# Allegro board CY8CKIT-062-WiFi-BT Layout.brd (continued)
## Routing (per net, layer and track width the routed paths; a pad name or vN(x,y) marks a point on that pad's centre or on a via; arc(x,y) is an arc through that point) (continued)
VDD_NS: length 21.2
  TOP w0.203: 81.74,45.44 81.74,44.48 U1.J1
  TOP w0.254: C24.1 82.26,45.97 81.74,45.44
  TOP w0.381: C18.1 C24.1
  L03_SIG w0.381: TP3.1 v1(69.95,53.97)
  L06_SIG w0.381: v1(69.95,53.97) 75.26,53.97 77.01,52.21 80.54,52.21 81.13,51.63 82.43,51.63 v1(82.5,51.56)
VDDA: length 35.5
  TOP w0.203: 89.61,37.46 89.38,37.46 88.98,37.06 87.21,37.06 U1.A12 ; U1.A13 87.12,36.68 88.98,36.68 89.5,36.15 89.61,36.15
  TOP w0.381: 89.61,36.15 C37.1 C38.1 ; C36.1 C35.1 89.61,37.46
  L06_SIG w0.381: TP26.1 117.78,35.48 111.23,35.48 108.97,37.73 v1(93.76,37.73)
VDDD: length 27.8
  TOP w0.203: 87.34,44.93 87.34,44.7 U1.A1 ; U1.L4 v2(80.25,42.15) ; U1.C4 v2(85.45,42.15) ; U1.K12 v2(80.9,36.95)
  TOP w0.254: C26.1 87.34,44.93
  TOP w0.381: C26.1 C20.1
  L05_MIX w0.381: 110.77,59.12 TP2.1 ; TP2.1 111.86,58.03 ; TP2.1 111.86,60.22 ; TP2.1 112.95,59.12
  BOTTOM w0.254: v2(85.45,42.15) 85.45,41.68 C100.1 ; v2(80.25,42.15) 80.58,42.15 81.25,41.49 C101.1 ; v2(80.9,36.95) 80.96,36.89 C114.1
  BOTTOM w0.381: v1(105.77,53.62) 104.37,53.62 SW7.1 ; v1(78.33,51.5) 78.71,51.88 R91.1 ; v1(82.25,39.09) v1(81.1,39.09) 81.25,39.24 C105.1 C101.1 ; R147.1 78.97,31.92 v1(78.97,32.58) ; v1(83.9,39.09) v1(85.17,39.09) 85.02,39.24 C104.1 C100.1 ; v1(80.65,32.94) 80.76,33.05 v1(80.76,34.01) 80.96,34.21 C117.1 C114.1
  vias: v1(86.84,51.66) v1(88.34,51.66)
VDDUSB: length 6
  TOP w0.203: U1.M1 79.45,44.82 79.45,45.06
  TOP w0.254: 79.45,46.96 79.45,45.06
  TOP w0.381: 79.45,46.96 C22.1 78.82,46.98 C21.1 ; 72.49,47.42 TP10.1 73.36,46.55
VIN: length 51.4
  TOP w0.381: v1(11.98,46.69) 11.8,46.87 R16.1
  L03_SIG w0.381: v1(13.79,10.77) 13.79,44.87 v1(11.98,46.69)
  L04_MIX w0.381: 4.74,2.36 J9.2 2.27,2.36 ; 45.16,15.65 J1.1 ; J1.1 45.16,17.83 ; J1.1 46.25,16.74
  BOTTOM w0.381: 45.16,15.65 J1.1 ; J1.1 44.07,16.74 ; J1.1 45.16,17.83 ; J1.1 46.25,16.74
  BOTTOM w0.635: 1.75,2.35 1.76,2.36 J9.2 5.05,2.36 5.05,2.35
  vias: v1(5.18,3.24) v1(7.34,1.85) v1(13.56,1.97) v1(17.5,2.23) v1(26.52,11.63) v1(29.57,11.63) v1(32.49,11.63) v1(45.57,18.86) v1(46.33,18.86) v1(47.6,14.93) v1(47.73,17.47)
VIN_MON: length 5.6
  TOP w0.254: U3.25 13.5,51.33 C15.1
  TOP w0.381: R16.2 12.84,49.31 R14.2 12.83,50.66 C15.1
ANT: length 3
  TOP w0.254: U6.41 122.22,57.9
  TOP w0.559: C4.2 122.22,58.96 L11.1 122.24,57.92 122.22,57.9
BT_DEV_WAKE_P4_0: length 61.2
  TOP w0.114: U1.L7 v2(80.25,40.2) ; U6.39 123.12,56.72 v1(122.78,56.38)
  L03_SIG w0.114: v1(122.78,56.38) 119.25,52.85 119.25,49.01 120.24,48.02 120.24,46.65 119.61,46.02 v1(119.61,45.03)
  L06_SIG w0.114: v2(80.25,40.2) 82.47,40.2 82.8,40.53 87.2,40.53 87.73,41.06 89.04,41.06 89.71,41.73 103.58,41.73 104.67,42.82 108.94,42.82 110.21,41.55 113.92,41.55 115.01,42.64 116.31,42.64 118.66,45 119.58,45 v1(119.61,45.03)
  BOTTOM w0.114: TP35.1 121.95,54.4 121.95,55.54 v1(122.78,56.38)
BT_GPIO_3: length 22.7
  TOP w0.114: TP22.1 123.42,37.15 v1(123.16,37.15) ; U6.6 121.41,54.3 121.11,54 120.51,54 118.24,51.73 118.24,48.56 v1(118.72,48.07)
  BOTTOM w0.114: v1(118.72,48.07) 118.72,47.55 120.14,46.13 120.31,46.13 120.6,45.83 120.6,43.65 122.91,41.34 122.91,37.41 v1(123.16,37.15)
BT_GPIO_4: length 25.8
  TOP w0.114: v1(123.16,36.26) 125.07,36.26 TP23.1 ; v1(119.23,46.3) 119.2,46.32 119.2,48.27 118.5,48.97 118.5,51.62 120.56,53.67 121.29,53.67 121.47,53.85 U6.7
  BOTTOM w0.114: v1(123.16,36.26) 122.66,36.77 122.66,41.22 119.1,44.77 119.1,46.17 v1(119.23,46.3)
BT_GPIO_5: length 14.4
  TOP w0.114: v1(122.4,48.05) 122.17,48.28 122.17,51.32 U6.13 ; TP17.1 125.7,41.47 v1(123.67,41.47)
  L03_SIG w0.114: v1(123.67,41.47) 124.11,41.91 124.11,45.83 122.4,47.54 v1(122.4,48.05)
BT_HOST_WAKE_P3_5: length 63.6
  TOP w0.114: U6.38 123.57,57.76 123.7,57.88 v1(123.7,57.88) ; v1(78.46,40.33) 79.23,41.1 U1.N6
  L03_SIG w0.114: v1(119.76,49.85) 120.57,50.67 120.57,53.38 123.39,56.2 123.39,57.58 v1(123.7,57.88)
  L06_SIG w0.114: v1(78.46,40.33) 78.79,40.66 78.79,43.74 80.77,45.71 87.15,45.71 87.7,45.16 91.4,45.16 92.96,46.73 94.52,46.73 95.07,46.17 110.18,46.17 111.25,47.24 113.65,47.24 116.51,50.11 119.51,50.11 v1(119.76,49.85)
  BOTTOM w0.114: v1(123.7,57.88) 123.2,57.38 122.94,57.38 TP31.1
BT_I2S_DO: length 16
  TOP w0.114: TP18.1 127.99,41.72 v1(127.99,42.87) ; v1(123.37,48.07) 122.85,48.59 122.85,49.54 123.57,50.26 U6.16
  L03_SIG w0.114: v1(127.99,42.87) 127.61,42.49 125.2,42.49 124.84,42.84 124.84,46.6 v1(123.37,48.07)
BT_PCM_CLK: length 18.8
  TOP w0.114: U6.11 120.75,52.05 120.37,51.66 120.37,51 121.21,50.16 121.21,47.44 123.72,44.92 130.23,44.92 131.8,43.35 TP15.1
BT_PCM_IN: length 16.4
  TOP w0.114: TP13.1 126.06,43.65 123.75,43.65 120.29,47.11 120.29,48 119.02,49.27 119.02,51.45 120.52,52.95 U6.9
BT_PCM_OUT: length 19
  TOP w0.114: U6.10 120.44,52.5 119.28,51.33 119.28,49.52 119.66,49.14 v1(120.07,49.14) ; TP14.1 v1(129.16,42.99)
  L06_SIG w0.114: v1(129.16,42.99) 129.18,42.99 129.18,44.21 128.12,45.28 122.66,45.28 121.06,46.88 121.06,48.15 v1(120.07,49.14)
BT_PCM_SYNC: length 24
  TOP w0.114: TP24.1 127.74,39.44 125.96,39.44 125.45,39.95 v1(123.42,39.95) ; v1(119.74,47.19) 119.74,48.08 119.43,48.38 119.43,48.39 118.75,49.07 118.75,51.52 120.62,53.4 U6.8
  BOTTOM w0.114: v1(123.42,39.95) 123.16,40.2 123.16,41.47 120.85,43.78 120.85,46.07 v1(119.74,47.19)
BT_REG_ON_P3_4: length 50.4
  TOP w0.114: U6.14 v1(122.67,50.72) ; U1.M6 v2(79.6,40.85)
  L03_SIG w0.114: v1(122.67,50.72) 121.23,49.28 121.23,46.78 v1(120.12,45.66)
  L06_SIG w0.114: v2(79.6,40.85) 79.92,40.53 82.39,40.53 82.63,40.76 85.47,40.76 85.89,41.18 87.53,41.18 87.64,41.29 88.63,41.29 89.45,42.11 103.42,42.11 104.51,43.2 108.94,43.2 109.5,42.64 114.27,42.64 114.72,43.1 116.05,43.1 118.62,45.66 v1(120.12,45.66)
BT_UART_CTS: length 6.6
  TOP w0.114: U6.4 121.25,55.2 121.01,54.96 118.32,54.96 R202.2 116.26,57.02 TP42.1
BT_UART_RTS: length 3.7
  TOP w0.114: U6.5 121.28,54.75 120.88,54.35 119.84,54.35 TP43.1 118.8,53.31 R203.2
BT_UART_RXD: length 5.3
  TOP w0.114: U6.2 120.94,56.1 R200.2 120.25,56.81 120.02,57.04 120.02,58.64 TP40.1
BT_UART_TXD: length 6.2
  TOP w0.114: U6.3 120.33,55.65 R201.2 120.25,56.02 120.09,56.18 118.64,56.18 118.47,56.35 118.47,57.29 TP41.1
CAP_BUT0_P8_1: length 20.9
  TOP w0.203: R61.1 v1(95.2,19.15)
  L06_SIG w0.203: v1(95.2,19.15) 96.11,18.24 96.11,13.91 99.54,10.48 v1(102.21,10.48) ; v1(102.84,7.69) v1(109.19,7.69)
CAP_BUT1_P8_2: length 42.7
  TOP w0.178: R60.1 v1(95.15,21.06)
  L06_SIG w0.203: v1(130.02,7.69) v1(124.56,7.69) ; v1(123.55,10.48) 120.12,13.91 97.89,13.91 96.75,15.05 96.75,20.39 96.08,21.06 v1(95.15,21.06)
CAP_PROX_P8_0: length 12.7
  TOP w0.203: J13.1 J13.2 R64.1 R63.1
CAP_SEG0_P8_3: length 10.2
  TOP w0.178: R53.1 95.17,26.77 v1(95.17,26.76)
  L06_SIG w0.203: v1(95.17,26.76) 102.31,26.76 v1(103.48,25.6)
CAP_SEG1_P8_4: length 18.9
  TOP w0.178: v1(95.17,28.64) 95.14,28.68 R52.1
  L06_SIG w0.203: v1(95.17,28.64) 96.29,28.64 97.84,30.19 97.84,32.02 98.15,32.33 107.54,32.33 108.18,31.69 v1(108.18,30.04)
CAP_SEG2_P8_5: length 24.5
  TOP w0.178: R47.1 v1(95.25,30.58)
  L06_SIG w0.203: v1(95.25,30.58) 95.39,30.73 96.8,30.73 97.13,31.06 97.13,32.58 97.51,32.96 113.13,32.96 114.15,31.95 v1(114.15,30.04)
CAP_SEG3_P8_6: length 36.2
  TOP w0.178: R58.1 v1(95.15,24.87)
  L06_SIG w0.203: v1(120.24,18.74) 120.24,17.47 118.34,15.56 98.78,15.56 98.09,16.25 98.09,22.85 96.08,24.87 v1(95.15,24.87)
CAP_SEG4_P8_7: length 42.7
  TOP w0.178: R59.1 95.17,22.96 v1(95.17,22.95)
  L06_SIG w0.203: v1(126.21,18.74) 126.21,15.56 125.45,14.8 98.4,14.8 97.51,15.69 97.51,21.53 96.09,22.95 v1(95.17,22.95)
CAP_TX_P1_0: length 59.9
  TOP w0.203: R62.2 v1(93.81,15.82)
  L03_SIG w0.203: v1(105.89,6.55) v1(105.89,8.96) ; v1(93.81,15.82) 94.51,15.12 94.51,13.12 96.66,10.98 96.66,6.48 99.47,3.68 v1(104.24,3.68) 124.23,3.68 v1(127.23,6.67) v1(127.23,8.83) 127.23,14.7 v1(124,17.92)
CC1: length 31.3
  TOP w0.114: U3.5 22.36,50.83 v1(22.43,50.9) ; J10.A5 8.04,52.97 8.61,53.54 8.61,55.57 v1(8.1,56.08)
  BOTTOM w0.114: v1(22.43,50.9) 21.89,51.44 21.89,57.53 20.65,58.78 14.39,58.78 12.7,60.47 10.46,60.47 8.57,58.58 C60.1 8.84,57.29 TVS2.1 8.11,56.06 v1(8.1,56.08)
CC2: length 38.1
  TOP w0.114: U3.3 22.37,49.83 v1(22.43,49.89)
  L06_SIG w0.114: J10.B5 3.32,52.79 3.32,57.16 5.18,59.02 v1(10.62,59.02)
  BOTTOM w0.114: TVS2.2 9.49,57.3 C59.1 9.75,58.15 v1(10.62,59.02) 12.4,59.02 13.03,58.39 20.38,58.39 21.59,57.18 21.59,50.72 v1(22.43,49.89)
CCG_12V_EN: length 55.1
  TOP w0.114: v1(18.03,45.56) 18.24,45.77 U3.35
  L03_SIG w0.114: v1(6.96,47.19) 6.96,44.42 7.98,43.4 7.98,11.38 v1(8.84,10.52)
  L06_SIG w0.114: v1(6.96,47.19) 10.08,47.19 12.93,44.34 17.48,44.34 18.03,44.9 v1(18.03,45.56)
  BOTTOM w0.114: U31.4 9,10.68 v1(8.84,10.52) R184.2
CCG_LED: length 30.7
  TOP w0.114: v1(10.21,43.63) 11.35,42.49 15.98,42.49 17.15,43.66 17.15,44.99 17.27,45.11 17.27,46.35 17.74,46.82 U3.34 ; LED7.K v1(11.71,59.92)
  L03_SIG w0.114: v1(11.71,59.92) 11.71,58.92 10.02,57.23 10.02,49.38 10.32,49.09 10.32,43.74 v1(10.21,43.63)
CCG_O_EN: length 26.4
  TOP w0.114: U3.38 19.74,46.25 v1(19.76,46.23)
  L03_SIG w0.114: v1(20.02,56.06) 19.76,55.8 v1(19.76,46.23)
  L06_SIG w0.114: v1(20.02,56.06) 21.67,54.4 28.92,54.4 v1(30.18,55.65)
  BOTTOM w0.114: v1(30.18,55.65) U13.2 26.93,55.65 R84.2
CCG_SWDCLK: length 14.1
  TOP w0.114: U3.16 18.24,54.76 18.36,54.88 18.36,56.36 19.12,57.12 24.47,57.12 25.63,55.96 25.63,53.92 TP36.1
CCG_SWDIO: length 16
  TOP w0.114: TP38.1 24.41,51.33 23.83,51.92 23.83,52.95 25.35,54.48 25.35,55.8 24.28,56.87 19.28,56.87 18.74,56.33 U3.15
CCG_VBUS_OUT: length 38.5
  TOP w0.203: v1(21.03,45.44) 20.67,45.8 20.67,47.27 20.74,47.34 U3.40
  L03_SIG w0.203: v1(10.19,41.65) 10.55,42.01 11.59,42.01 12.37,41.23 12.37,31.26 10.11,29 10.11,27.08 10.57,26.62 11.02,26.62 v1(11.25,26.39)
  L06_SIG w0.203: v1(21.03,45.44) 20.62,45.03 20.62,44.35 19.28,43 15.28,43 14.27,41.99 10.52,41.99 v1(10.19,41.65)
  BOTTOM w0.203: R154.1 13.14,25.95 12.7,26.39 v1(11.25,26.39)
CCG_VCCD: length 4.6
  TOP w0.203: v1(15.95,55.47) 16.46,55.47 16.74,55.19 U3.19
  BOTTOM w0.381: C72.1 15.3,54.82 v1(15.95,55.47) 16.56,54.86 C71.1
CCG_VDD: length 3.9
  TOP w0.203: U3.17 17.74,55.21 v1(17.48,55.47) ; v1(17.48,55.47) 17.24,55.24 U3.18 ; v1(17.48,55.47) v1(17.48,56.49)
CCG_VSYS: length 17
  TOP w0.203: 14.18,53.7 14.61,54.13 U3.20
  TOP w0.381: C8.1 15.06,55.48 14.17,54.58 v1(14.17,53.7) 14.18,53.7 ; v1(43.03,56.38) 43.36,56.05 D1.K D2.K
  L03_SIG w0.381: TP29.1 24.94,60.32 ; TP29.1 24.41,60.85 ; TP29.1 23.88,60.32 ; TP29.1 24.41,59.79
  L06_SIG w0.381: TP29.1 24.41,60.85 ; TP29.1 23.88,60.32 ; TP29.1 24.94,60.32 ; TP29.1 24.41,59.79
  BOTTOM w0.381: TP29.1 24.39,60.3 R75.1 v1(22.82,59.39) ; v1(14.17,52.68) 14.17,52.39 14.39,52.17 C77.1 15.3,52.16 C79.1
  vias: v1(43.64,56.94)
CCG_XRES_L: length 27.1
  TOP w0.114: U3.26 14.36,50.83 v1(14.17,50.65)
  L03_SIG w0.114: v1(14.17,50.65) 13.2,50.65 12.57,51.27 12.57,57.9 15.57,60.9 v1(18.39,60.9)
  L06_SIG w0.114: v1(18.39,60.9) 24.05,55.24 TP32.1
  BOTTOM w0.114: C83.1 14.62,49.68 14.17,50.13 v1(14.17,50.65)
CE_L: length 31.7
  TOP w0.114: U3.10 22.32,53.33 v1(22.43,53.44)
  TOP w0.152: R4.2 45.93,52.05 C14.1 46.69,52.04 v1(46.81,51.92) R11.2
  L06_SIG w0.114: v1(46.81,51.92) 44.98,53.75 42.6,53.75 42.5,53.64 40.63,53.64 40.15,54.13 23.11,54.13 v1(22.43,53.44)
  BOTTOM w0.114: v1(46.81,51.92) 46.61,52.12 U19.4
CHG_L: length 3.1
  BOTTOM w0.114: U19.13 40.23,51.12 40.01,50.9 39.59,50.9 R102.1
DEV_USB_DM: length 43.5
  TOP w0.203: v1(109.07,61.89) 108.86,62.1 108.16,62.1 107.44,62.82 107.44,64.47 J28.A7
  L06_SIG w0.203: v1(83.39,53.99) 83.7,54.31 91.9,54.31 92.43,54.84 94.56,54.84 95.76,56.03 102.29,56.03 103.45,54.87 107.82,54.87 109.73,56.78 109.73,61.06 109.07,61.72 v1(109.07,61.89)
  BOTTOM w0.203: U16.4 84.72,54.33 83.73,54.33 v1(83.39,53.99)
  BOTTOM w0.229: v1(109.07,61.89) 109.12,61.94 109.12,63.34 107.98,64.48 107.98,65.74 J28.B7
DEV_USB_DP: length 41.6
  TOP w0.203: J28.A6 107.85,64.51 107.85,62.99 108.33,62.51 108.39,62.51 v1(108.51,62.63)
  L06_SIG w0.203: v1(108.51,62.63) 108.59,62.55 108.59,61.63 109.32,60.89 109.32,56.95 107.65,55.28 103.62,55.28 102.45,56.44 95.59,56.44 94.4,55.25 92.27,55.25 91.73,54.71 83.65,54.71 v1(83.39,54.97)
  BOTTOM w0.203: U16.5 84.72,54.73 83.62,54.73 v1(83.39,54.97)
  BOTTOM w0.229: v1(108.51,62.63) 108.51,63.09 107.37,64.23 107.37,65.71 J28.B6
DIGPOT_SCL: length 40.8
  TOP w0.114: v1(69.42,25.88) 69.9,25.4 69.9,22.75 67.95,20.79 56.97,20.79 54.08,23.69 48.56,23.69 47.66,24.6 47.66,25.44 47.09,26.01 47.09,28.98 45.78,30.29 U2.68
  BOTTOM w0.114: R155.2 72.43,25.73 U27.2 69.58,25.73 v1(69.42,25.88)
DIGPOT_SDA: length 38.2
  TOP w0.114: v1(69.42,24.74) 69.42,22.65 67.83,21.06 57.19,21.06 54.31,23.94 48.69,23.94 47.93,24.71 47.93,25.53 47.35,26.11 47.35,29.11 45.36,31.09 U2.1
  BOTTOM w0.114: v1(69.42,24.74) 69.75,25.07 U27.3 72.36,25.07 72.76,25.48 R157.2
ECO_P12_6: length 9.6
  BOTTOM w0.114: Y2.1 96.47,41.31 96.02,41.76 C99.1 93.04,41.63 R131.2
ECO_P12_7: length 7.6
  BOTTOM w0.114: Y2.2 96.47,43.47 96.02,43.03 C96.1 92.91,43.28 R126.2
FLASH_CS_P11_2: length 60
  TOP w0.114: U4.C2 v1(115.26,41.01) ; v1(82.89,17.31) 82.89,24.68 82.37,25.2 82.37,30.68 84.87,33.17 86.94,33.17 87.81,32.31 90.76,32.31 91.03,32.58 96.74,32.58 97.23,33.07 107.35,33.07 v1(108.18,33.9)
  L03_SIG w0.114: v1(108.18,33.9) 109.09,34.82 v1(109.09,41.34)
  BOTTOM w0.114: v1(109.09,41.34) 114.93,41.34 v1(115.26,41.01) 115.26,40.61 115.54,40.33 R134.2 ; v1(82.89,17.31) 82.27,16.69 R176.2
FRAM_CS_P11_0: length 42.3
  TOP w0.114: v1(101.68,36.7) 101.19,37.18 R39.2 103.83,37.79 103.96,37.91 U5.1 ; v1(100.36,33.77) 99.95,33.37 96.99,33.37 96.48,32.86 90.88,32.86 90.62,32.6 87.96,32.6 87.07,33.49 84.84,33.49 82.12,30.77 82.12,24.91 82.56,24.48 82.56,19.48 v1(82.21,19.13)
  L03_SIG w0.114: v1(101.68,36.7) 101.68,35.1 v1(100.36,33.77)
  BOTTOM w0.114: R173.2 v1(82.21,19.13)
FRAM_VDD: length 4.3
  TOP w0.381: 109.13,54.81 J26.1 ; J26.1 110.21,55.89 ; J26.1 111.29,54.81 ; J26.1 110.21,53.72
HOST_USB_DM: length 8.5
  TOP w0.203: v1(84.66,55.77) 85.53,56.64 88.81,56.64 89.26,57.08 89.26,57.51 89.97,58.23 J27.2
  BOTTOM w0.203: v1(84.66,55.77) 84.99,56.11 85.3,56.11 85.47,55.94 85.47,55.09 U16.6
HOST_USB_DP: length 8
  TOP w0.203: J27.3 88.05,58.23 88.65,57.63 88.65,57.31 88.38,57.05 84.96,57.05 v1(84.66,56.75)
  BOTTOM w0.203: U16.7 85.87,56.11 85.47,56.51 84.89,56.51 v1(84.66,56.75)
I2C_SCL: length 45.3
  TOP w0.114: v1(31.85,37.66) 32.23,37.66 32.59,37.3 R40.1 32.98,36.29 U2.38 ; R30.1 19.74,42.36 v1(19.74,40.99)
  L03_SIG w0.114: v1(31.14,42.16) 31.85,41.45 v1(31.85,37.66) ; v1(6.6,39.54) 6.12,39.06 6.12,36.61 J6.6
  L06_SIG w0.114: v1(31.14,42.16) 29.38,40.4 20.83,40.4 20.24,40.99 v1(19.74,40.99) 19.2,40.99 17.75,39.54 v1(6.6,39.54)
  BOTTOM w0.114: J6.6 4.82,35.27 R141.1
I2C_SCL_EC: length 4.1
  TOP w0.114: R30.2 19.23,44.71 19.23,48.02 U3.37
I2C_SDA: length 58.6
  TOP w0.114: R29.1 v1(18.11,40.94) ; U2.39 33.07,35.89 R43.1 32.59,34.55 v1(32.11,34.06)
  L03_SIG w0.114: v1(6.58,40.94) 7.52,40 7.52,32.92 J6.10 ; v1(31.17,43.07) 32.33,41.9 32.33,34.29 v1(32.11,34.06)
  L06_SIG w0.114: v1(31.17,43.07) 28.78,40.68 21.23,40.68 20.32,41.6 18.77,41.6 v1(18.11,40.94) 17,39.83 7.69,39.83 v1(6.58,40.94)
  BOTTOM w0.114: J6.10 4.81,30.21 R150.1
I2C_SDA_EC: length 4.1
  TOP w0.114: U3.36 18.74,44.81 R29.2
IN_N: length 6.2
  BOTTOM w0.114: U21.3 73.68,45.96 73.25,45.53 72.11,45.53 70.84,46.81 R106.1 70.83,47.83 C84.1
IUSB1: length 27.2
  TOP w0.114: R1.1 R2.1 39.73,53.42 v1(39.95,53.19) 39.01,52.25 39.01,49.98 37.64,48.61 35.46,48.61 35.15,48.91 23.87,48.91 23.06,49.71 23.06,51.22 22.46,51.83 U3.7
  BOTTOM w0.114: v1(39.95,53.19) 40.02,53.12 U19.17
IUSB2: length 25.6
  TOP w0.114: v1(38.43,53.19) 38.31,53.06 R6.1 R9.1 38.31,49.85 37.34,48.89 35.61,48.89 35.33,49.17 24.01,49.17 23.34,49.83 23.34,51.31 22.32,52.33 U3.8
  BOTTOM w0.114: v1(38.43,53.19) 39.07,53.19 39.63,52.62 U19.16
IUSB3: length 23.5
  TOP w0.114: R10.1 40.97,50.27 R5.1 40.21,51.79 v1(39.95,51.54) ; U3.9 22.8,52.83 v1(22.86,52.77)
  L06_SIG w0.114: v1(22.86,52.77) 23.83,53.75 34.94,53.75 37.15,51.54 v1(39.95,51.54)
  BOTTOM w0.114: U19.14 40.04,51.62 v1(39.95,51.54)
J1_3V3: length 5.7
  L04_MIX w0.381: 33.91,16.74 J1.5 ; J1.5 35,17.83 ; J1.5 36.09,16.74 ; J1.5 35,15.65
  BOTTOM w0.254: v1(49.5,21.91) 49.51,21.92 U28.4 49.13,22.92
  vias: v1(48.87,21.91)
J1_5V0: length 10.4
  TOP w0.381: 37.54,15.65 J1.4 ; J1.4 36.45,16.74 ; J1.4 38.63,16.74 ; J1.4 37.54,17.83
  BOTTOM w0.254: v1(46.96,21.79) 47.22,22.04 U29.4 46.83,22.92
  BOTTOM w0.381: 37.54,15.65 J1.4 ; J1.4 38.63,16.74 ; J1.4 36.45,16.74 ; J1.4 37.54,17.83
  vias: v1(46.2,21.91)
J2_P9_3: length 3
  BOTTOM w0.114: R162.2 58.95,21.16 58.95,20.37 J2.8
J18_P7_0: length 30
  TOP w0.114: J18.6 34.81,11.88 41.08,11.88 42.1,10.86 48.49,10.86 49.12,11.5 v1(57.38,11.5)
  BOTTOM w0.114: R181.2 58.18,13.7 57.38,12.9 v1(57.38,11.5)
J18_P7_3: length 59.8
  TOP w0.114: v1(70.71,11.88) 70.51,11.68 57.96,11.68 57.69,11.94 41.48,11.94 41.15,12.27 36.96,12.27 J18.5
  L03_SIG w0.114: v1(70.71,11.88) 71.73,12.9 71.73,20.52 70.71,21.53 70.71,27.63 70.33,28.01 v1(70.33,32.45)
  BOTTOM w0.114: R146.1 70.72,32.06 v1(70.33,32.45)
J18_P7_4: length 33.9
  TOP w0.114: J18.4 39.18,12.59 41.26,12.59 41.66,12.19 58.29,12.19 58.52,11.96 66.98,11.96 v1(67.67,12.64)
  BOTTOM w0.114: R178.2 67.39,13.7 67.66,13.43 67.66,12.64 v1(67.67,12.64)
J18_P7_5: length 25.6
  TOP w0.114: v1(62.33,12.87) 61.72,12.26 58.6,12.26 58.4,12.46 41.85,12.46 J18.3
  BOTTOM w0.114: v1(62.33,12.87) 62.36,12.87 63.19,13.7 R179.2
J18_P7_6: length 20.7
  TOP w0.114: v1(60.1,12.97) 59.82,12.7 42.85,12.7 42.65,12.9 J18.2
  BOTTOM w0.114: v1(60.1,12.97) 60.1,13.43 60.37,13.7 R180.2
J18_P7_7: length 49.8
  L06_SIG w0.114: v1(48.74,14.17) 48.71,14.2 J18.1
  BOTTOM w0.114: R142.2 79.6,32.95 79.6,31.31 77.32,29.02 77.32,25.09 74.78,22.55 64.49,22.55 61.7,19.75 61.7,15.69 60.93,14.93 49.5,14.93 v1(48.74,14.17)
J18_P11_0: length 60.5
  L06_SIG w0.114: v1(82.3,11.37) 80.85,12.82 76.56,12.82 76.23,13.15 69.82,13.15 68.8,14.17 52.04,14.17 50.71,15.5 28.71,15.5 J18.8
  BOTTOM w0.114: R175.2 84.05,12.26 83.16,11.37 v1(82.3,11.37)
J18_P11_2: length 55.8
  L06_SIG w0.114: v1(80.95,11.27) 79.65,12.57 76.19,12.57 75.87,12.9 69.57,12.9 68.6,13.87 51.31,13.87 49.89,12.44 31.71,12.44 J18.7
  BOTTOM w0.114: v1(80.95,11.27) 80.95,13.06 R177.2
J19_P1_0: length 135
  L03_SIG w0.203: v1(95.26,17.25) 98.19,20.18 98.19,34.38 98.19,34.38 98.19,34.42 98.19,34.46 98.21,34.52 98.23,34.59 98.27,34.65 98.3,34.67 101.42,37.8 101.42,37.81 101.5,37.89 101.5,39.53 105,43.03 105,53.79 105.51,54.3 107.7,54.3 108.8,55.4 108.82,55.42 108.83,55.43 109.58,56.18 109.58,59.45 v1(108.15,60.88)
  L06_SIG w0.203: J19.5 33.36,70.05 95.02,70.05 102.84,62.22 105.26,62.22 106.6,60.88 v1(108.15,60.88)
  BOTTOM w0.203: v1(95.26,17.25) R174.2
J19_P12_4: length 52.9
  TOP w0.114: v1(62.6,59.58) 60.82,61.37 44.36,61.37 44.1,61.11 34.74,61.11 34.08,61.77 20.39,61.77 19.33,62.83 19.33,66.42 J19.10
  BOTTOM w0.114: v1(62.6,59.58) 62.6,61.22 62.81,61.42 R74.2
J19_P12_5: length 53.6
  TOP w0.114: v1(66.32,61.42) 65.72,61.42 65.51,61.64 44.1,61.64 43.84,61.38 34.86,61.38 34.21,62.02 20.58,62.02 19.58,63.02 19.58,66.42 J19.9
  BOTTOM w0.114: R73.2 v1(66.32,61.42)
J19_P12_6: length 101.7
  TOP w0.114: v1(95.99,53.66) 94.84,52.52 94.84,41.47 95.48,40.84 v1(95.48,39.95)
  L06_SIG w0.114: v1(95.99,53.66) 94.75,53.66 93.95,52.86 90.21,52.86 88.37,51.02 77.11,51.02 75.63,49.55 60.93,49.55 51.16,59.33 33.05,59.33 29.29,63.09 26.16,63.09 24.59,64.66 24.59,66.24 J19.8
  BOTTOM w0.114: R135.2 92.46,39.18 94.71,39.18 v1(95.48,39.95)
J19_P12_7: length 89.1
  TOP w0.114: v1(94.23,46.19) 94.41,46.37 94.41,52.75 v1(93.73,53.43)
  L06_SIG w0.114: v1(93.73,53.43) 89.15,53.43 88.24,52.52 87.1,52.52 86.55,53.06 85.13,53.06 84.33,52.27 81.28,52.27 80.87,52.67 77.16,52.67 75.34,54.5 68.42,54.5 66.12,52.19 58.67,52.19 51.28,59.58 33.3,59.58 29.29,63.59 27.48,63.59 27.13,63.95 27.13,66.35 J19.6
  BOTTOM w0.114: v1(94.23,46.19) 93.36,45.31 92.04,45.31 R120.2
J20_P8_0: length 94.4
  TOP w0.203: R64.2 92.44,14.81 v1(92.56,14.93)
  L03_SIG w0.203: J20.1 64.25,66.24 75.11,66.24 77.17,68.29 94.88,68.29 99.42,63.76 99.42,61.38 100.27,60.53 100.27,45.41 96.34,41.49 96.34,39.5 92.49,35.66 92.49,14.99 v1(92.56,14.93)
J20_P8_1: length 94.3
  L03_SIG w0.203: J20.2 61.73,68.88 95.12,68.88 101.9,62.1 101.9,57.62 100.86,56.57 100.86,45.17 96.93,41.24 96.93,39.26 93.08,35.41 93.08,22.09 95.03,20.13 v1(95.73,20.13)
  BOTTOM w0.203: v1(95.73,20.13) 94.87,20.13 93.89,19.15 R172.2
J20_P8_2: length 96.2
  L03_SIG w0.203: J20.3 59.78,69.46 95.43,69.46 102.49,62.4 102.49,57.38 101.44,56.33 101.44,44.93 97.56,41.05 97.56,39.07 93.66,35.17 93.66,22.99 94.64,22.01 v1(95.73,22.01)
  BOTTOM w0.203: R166.2 93.89,21.06 94.84,22.01 v1(95.73,22.01)
J20_P8_3: length 93.8
  L03_SIG w0.203: J20.4 57.82,70.05 95.73,70.05 99.48,66.29 99.5,66.27 99.53,66.25 103.07,62.7 103.07,57.07 102.02,56.02 102.02,44.49 98.17,40.63 98.17,38.85 97.98,38.67 94.25,34.93 94.25,28.53 95.15,27.63 v1(95.73,27.63)
  BOTTOM w0.203: R153.2 93.89,26.77 94.74,27.63 v1(95.73,27.63)
J20_P8_4: length 93.6
  TOP w0.203: J20.5 54.11,68.88 95.25,68.88 103.28,60.85 104.04,60.85 v1(104.7,60.19)
  L03_SIG w0.203: v1(95.73,29.53) 96.44,30.24 96.44,35.38 99.47,38.41 99.47,40.05 103.25,43.83 103.25,55.19 105.77,57.7 105.77,59.12 v1(104.7,60.19)
  BOTTOM w0.203: R152.2 93.89,28.68 94.74,29.53 v1(95.73,29.53)
J20_P8_5: length 95.4
  TOP w0.203: J20.6 52.16,69.46 95.49,69.46 103.44,61.51 104.46,61.51 105.51,60.46 105.51,59.89 v1(104.65,59.02)
  L03_SIG w0.203: v1(104.65,59.02) 103.73,58.11 103.73,56.76 102.67,55.69 102.67,44.16 98.86,40.35 98.86,38.63 95.85,35.62 95.85,31.74 v1(95.7,31.59)
  BOTTOM w0.203: R149.2 93.81,31.19 94.21,31.59 v1(95.7,31.59)
J20_P8_6: length 108
  TOP w0.203: v1(107.54,58.26) 107.54,59.25 104.62,62.17 103.76,62.17 95.88,70.05 50.2,70.05 J20.7
  L03_SIG w0.203: v1(107.54,58.26) 108.18,57.62 108.18,56.47 107.35,55.64 104.82,55.64 103.84,54.65 103.84,43.55 100.1,39.82 100.1,38.19 97.02,35.12 97.02,27.14 v1(95.73,25.85)
  BOTTOM w0.203: v1(95.73,25.85) 94.89,25.85 93.91,24.87 R158.2
J20_P8_7: length 112.7
  L03_SIG w0.203: v1(108.36,58.64) 108.99,58.01 108.99,56.46 107.53,54.99 105.19,54.99 104.42,54.22 104.42,43.27 100.84,39.69 100.84,38.04 97.61,34.81 97.61,25.69 v1(95.73,23.82)
  L06_SIG w0.203: v1(108.36,58.64) 107.96,59.04 107.59,59.04 104.98,61.64 102.59,61.64 94.77,69.46 47.08,69.46 J20.8
  BOTTOM w0.203: R160.2 93.89,22.96 94.74,23.82 v1(95.73,23.82)
KP2_SWCLK: length 72.3
  TOP w0.114: U2.47 35.3,32.69 v1(34.77,33.22)
  L03_SIG w0.114: v1(34.77,33.22) 35.28,32.71 35.28,29.68 37.19,27.78 37.19,25.7 35.79,24.3 35.79,18.61 36.17,18.23 36.17,10.36 v1(35.92,10.1)
  L06_SIG w0.114: v1(76.93,10.49) 76.06,9.63 73.96,9.63 73.41,10.19 69.22,10.19 68.66,9.63 61.01,9.63 59.27,11.37 58.14,11.37 57.89,11.12 57.89,10.48 57.63,10.23 57,10.23 55.98,11.24 53.82,11.24 52.68,10.1 v1(35.92,10.1)
  BOTTOM w0.114: R183.2 v1(76.93,10.49)
KP2_SWD_RST_L: length 63.8
  TOP w0.114: v1(46.84,32.58) 46.15,31.89 U2.3
  L03_SIG w0.114: v1(46.84,32.58) 45.44,31.18 45.44,24.2 47.47,22.17 47.47,19.12 47.09,18.74 v1(47.09,11.37)
  L06_SIG w0.114: v1(78.46,11.75) 77.95,12.26 76.24,12.26 75.23,11.24 61.7,11.24 60.75,12.19 58.21,12.19 56.79,13.61 51.64,13.61 49.4,11.37 v1(47.09,11.37)
  BOTTOM w0.114: v1(78.46,11.75) 78.65,11.94 80.04,11.94 80.29,11.68 R182.2
KP2_SWDIO: length 62.2
  TOP w0.114: U2.46 35.79,33.09 v1(35.53,33.34)
  L03_SIG w0.114: v1(35.53,33.34) 35.53,29.79 37.44,27.88 37.44,25.6 36.04,24.2 36.04,18.86 36.42,18.48 v1(36.42,9.47)
  L06_SIG w0.114: v1(69.57,8.64) 57.45,8.64 56.24,9.85 36.8,9.85 v1(36.42,9.47)
  BOTTOM w0.114: v1(69.57,8.64) 70.01,8.64 R194.2
KP_PMIC_EN: length 95.9
  TOP w0.114: v1(104.47,57.73) 103.99,57.73 103.24,58.48 R197.1 ; v1(46.81,30.71) 46.03,31.49 U2.2
  L06_SIG w0.114: v1(104.47,57.73) 102.31,59.89 100.36,59.89 97.57,62.67 86.21,62.67 84.54,64.33 82.14,64.33 78.71,60.9 74.78,60.9 73.56,59.68 65.32,59.68 63.49,61.51 55.22,61.51 v1(54.25,60.55)
  BOTTOM w0.114: v1(54.25,60.55) 51.92,58.21 51.92,46.07 49.25,43.4 49.25,39.77 46.94,37.46 46.94,34.82 46.25,34.13 46.25,32.51 46.94,31.82 46.94,30.84 v1(46.81,30.71) ; U12.2 v1(104.47,57.73)
KP_PMIC_EN_OUT: length 78.9
  TOP w0.381: v1(99.65,53.62) 99.65,55.44 98.15,56.95 98.15,63.09 95.77,65.46 91.61,65.46 90.83,66.24 82.6,66.24 77.41,61.04 72.78,61.04 71.48,59.73 69.24,59.73 67.84,58.34 v1(67.84,58.01)
  L03_SIG w0.381: v1(67.84,58.01) 67.84,57.22 68.51,56.56 68.51,50.15 71.48,47.19 71.48,38.3 71.75,38.03 71.75,28.91 v1(71.22,28.39)
  BOTTOM w0.381: U27.1 70.91,28.07 v1(71.22,28.39)
LPO_IN_32KHZ: length 4.5
  TOP w0.114: U6.37 124.02,56.57 v1(124.05,56.54)
  BOTTOM w0.114: U11.3 125.55,57.47 125.02,57.47 124.09,56.54 v1(124.05,56.54)
P0_0: length 5.9
  TOP w0.114: U1.E3 v2(84.72,43.37)
  BOTTOM w0.114: C86.1 84.41,46.95 Y1.1 83.79,45.91 84.39,45.3 84.39,43.7 v2(84.72,43.37)
P0_1: length 5.5
  TOP w0.114: U1.E2 v2(84.72,44.02)
  BOTTOM w0.114: C85.1 85.67,46.95 Y1.2 86.29,45.59 v2(84.72,44.02)
P0_2: length 72.4
  TOP w0.114: U1.E1 v2(84.72,44.67)
  L03_SIG w0.114: v2(84.72,44.67) 82.45,46.95 82.45,49.99 80.29,52.15 80.29,62.1 83.67,65.47 v1(86.84,65.47)
  L06_SIG w0.114: v1(86.84,65.47) 86.69,65.47 85.37,66.79 81.1,66.79 77.48,63.17 67.03,63.17 66.66,62.81 64.86,62.81 64.49,63.17 46.99,63.17 J4.8
P0_3: length 30.9
  TOP w0.114: R18.1 111.32,45.85 v1(111.3,45.84) ; U1.F3 v2(84.07,43.37)
  L06_SIG w0.114: v2(84.07,43.37) 84.39,43.7 84.81,43.7 84.81,43.7 84.85,43.7 85.05,43.89 85.05,44.16 85.24,44.35 86.8,44.35 86.99,44.16 86.99,43.89 87.19,43.7 88.56,43.7 88.93,44.06 99.8,44.06 100.92,45.18 105.18,45.18 105.18,45.18 110.64,45.18 v1(111.3,45.84)
P0_4: length 112.2
  TOP w0.114: SW2.B 15.4,6.1 16.41,7.1 v1(18.16,7.1) 19.48,5.78 34.26,5.78 36.4,7.92 72.85,7.92 73.38,8.45 v1(74.9,8.45) ; U1.F2 v2(84.07,44.02)
  L03_SIG w0.114: v1(74.9,8.45) 75.54,9.09 75.54,18.46 76.17,19.09 76.17,37.66 v1(75.41,38.42) 78.42,38.42 79.22,39.23 80.38,39.23 83.75,42.59 83.75,43.7 v2(84.07,44.02)
  BOTTOM w0.114: R68.2 R67.1 18.34,7.28 v1(18.16,7.1) ; v1(75.41,38.42) 76.94,39.95 R133.1
P0_5: length 25.6
  TOP w0.114: U1.G3 v2(83.42,43.37)
  L03_SIG w0.114: v1(98.17,45.2) 98.22,45.2 98.22,51.94 v1(97.76,52.39)
  L06_SIG w0.114: v1(98.17,45.2) 93.46,45.2 92.62,44.35 87.48,44.35 87.22,44.61 86.56,44.61 86.14,45.03 84.51,45.03 84.39,44.91 84.39,44.46 84.29,44.35 83.83,44.35 83.75,44.27 83.75,43.7 v2(83.42,43.37)
  BOTTOM w0.114: U20.2 v1(97.76,52.39)
P1_0: length 38.6
  TOP w0.203: v1(86.7,32.11) 88.49,30.32 88.49,18.9 v1(90.14,17.25) R62.1 ; U1.G2 v2(83.42,44.02)
  L03_SIG w0.114: v2(83.42,44.02) 83.6,44.02 83.93,44.35 85.5,44.35 85.69,44.16 85.69,42.36 85.77,42.29 85.77,42.02 85.62,41.87 85.62,40.79 85.89,40.53 86.86,40.53 86.9,40.56
  L03_SIG w0.203: 86.9,40.56 88.09,40.56 88.37,40.27 88.37,38.34 88.8,37.91 88.8,36.58 86.7,34.48 v1(86.7,32.11)
  BOTTOM w0.203: R62.1 v1(90.14,17.25)
P1_1: length 39
  TOP w0.114: R8.2 116.7,49.71 v1(117.07,49.34) ; U1.G1 v2(83.42,44.67)
  L06_SIG w0.114: v1(117.07,49.34) 116.56,49.34 113.92,46.7 111.47,46.7 110.43,45.66 97.58,45.66 97.38,45.47 93.1,45.47 92.24,44.61 87.6,44.61 86.96,45.26 84,45.26 v2(83.42,44.67)
P1_2: length 82.4
  TOP w0.114: v1(82.91,67.38) 81.74,67.38 76.81,62.45 69.49,62.45 68.94,61.9 43.85,61.9 42.85,62.91 35.74,62.91 34.57,64.08 34.57,66.42 J19.4 ; U1.H3 v2(82.2,43.37)
  L03_SIG w0.114: v1(82.91,67.38) 80.04,64.51 80.04,52.02 82.17,49.89 82.17,46.75 82.75,46.17 82.75,43.93 v2(82.2,43.37)
P1_3: length 77.6
  TOP w0.114: v1(79.1,67.38) 79.1,65.22 76.63,62.76 69.08,62.76 68.5,62.18 44.04,62.18 42.98,63.24 35.9,63.24 34.82,64.31 34.82,66.42 J19.3 ; U1.H2 v2(82.2,44.02)
  L03_SIG w0.114: v1(79.1,67.38) 79.78,66.69 79.78,51.87 81.92,49.73 81.92,46.53 82.52,45.92 82.52,44.35 v2(82.2,44.02)
P1_4: length 71.7
  TOP w0.114: U1.H1 v2(82.2,44.67) ; v1(78.15,67.52) 78.15,64.9 76.3,63.06 68.55,63.06 67.92,62.43 44.21,62.43 43.08,63.57 40.11,63.57 39.85,63.82 39.85,65.75 38.5,67.1 J19.2
  L03_SIG w0.114: v2(82.2,44.67) 82.2,45.84 81.66,46.37 81.66,49.63 79.53,51.76 79.53,66.14 v1(78.15,67.52)
P1_5: length 117
  TOP w0.114: v1(121.31,45.43) 121.53,45.22 R27.1 ; J19.1 42.21,67.56 43.03,66.74 43.03,64.33 44.67,62.69 67.51,62.69 68.17,63.34 76.07,63.34 77.32,64.58 v1(77.32,67.51) ; U1.J3 v2(81.55,43.37)
  L03_SIG w0.114: v2(81.55,43.37) 81.87,43.7 81.87,45.68 81.41,46.14 81.41,49.46 79.27,51.6 79.27,65.55 v1(77.32,67.51)
  L06_SIG w0.114: v1(121.31,45.43) 121.31,46.25 120.78,46.78 120.78,47.74 118.67,49.85 116.69,49.85 113.8,46.96 111.38,46.96 110.33,45.92 97.42,45.92 97.21,45.71 92.66,45.71 91.85,44.9 87.64,44.9 87.05,45.49 83.62,45.49 82.52,44.39 82.52,43.8 82.42,43.7 81.87,43.7 v2(81.55,43.37)
P2_0: length 4.3
  TOP w0.114: U1.M2 v2(79.6,44.02)
  BOTTOM w0.114: R122.1 79.59,44.01 v2(79.6,44.02)
P2_1: length 4
  TOP w0.114: U1.N2 79.13,43.63 76.57,43.63 R32.1
P2_2: length 5.5
  TOP w0.114: U1.L3 v2(80.25,43.37)
  BOTTOM w0.114: R128.1 76.64,43.7 79.92,43.7 v2(80.25,43.37)
P2_3: length 5.4
  TOP w0.114: U1.M3 v2(79.6,43.37)
  BOTTOM w0.114: R132.1 76.3,42.09 76.3,42.61 77.06,43.37 v2(79.6,43.37)
P2_4: length 4.4
  TOP w0.114: R36.1 77.46,43.25 79.07,43.25 U1.N3
P2_5: length 3.7
  TOP w0.114: R28.1 78.86,44.01 U1.N1
P3_0: length 52.4
  TOP w0.114: v1(117.6,56.69) 117.65,56.69 118.54,55.8 119.17,55.8 R201.1 ; U1.L5 v2(80.25,41.5)
  L03_SIG w0.114: v1(117.6,56.69) 118.67,55.62 118.67,54.17 116.05,51.55 116.05,48.33 v1(116.69,47.69)
  L06_SIG w0.114: v2(80.25,41.5) 81.9,41.5 83.14,42.75 88.71,42.75 89.21,43.25 101.5,43.25 102.57,44.32 112.01,44.32 113.64,45.95 114.23,45.95 115.98,47.69 v1(116.69,47.69)
P3_1: length 54.4
  TOP w0.114: U1.M5 v2(79.6,41.5) ; v1(119.43,57.98) 119.17,57.72 R200.1
  L03_SIG w0.114: v1(117.3,48.07) 116.43,48.94 116.43,51.48 119.63,54.68 119.63,57.78 v1(119.43,57.98)
  L06_SIG w0.114: v2(79.6,41.5) 79.92,41.18 81.98,41.18 83.32,42.52 88.93,42.52 89.27,42.87 102.11,42.87 103.25,44.01 112.08,44.01 113.77,45.69 114.33,45.69 115.82,47.19 116.94,47.19 117.3,47.54 v1(117.3,48.07)
P3_2: length 49.4
  TOP w0.114: v1(117.3,50.67) 117.3,52.98 117.93,53.61 R202.1 ; v1(77.95,41.98) 78.14,41.79 U1.N5
  L06_SIG w0.114: v1(117.3,50.67) 116.71,50.67 113.55,47.5 111.12,47.5 110.05,46.42 95.2,46.42 94.58,47.05 90.79,47.05 90.02,46.27 88.13,46.27 87.8,45.94 80.62,45.94 78.41,43.73 78.41,42.44 v1(77.95,41.98)
P3_3: length 47.4
  TOP w0.114: v1(118.01,48.07) 117.96,48.13 117.96,52.32 R203.1 ; U1.L6 v2(80.25,40.85)
  L06_SIG w0.114: v2(80.25,40.85) 82.11,40.85 83.08,41.83 87.53,41.83 87.71,42.01 88.91,42.01 89.38,42.49 102.75,42.49 103.84,43.58 108.99,43.58 109.68,42.89 113.98,42.89 114.57,43.48 115.67,43.48 118.01,45.81 v1(118.01,48.07)
P4_1: length 38.6
  TOP w0.114: U1.M7 v2(79.6,40.2)
  L03_SIG w0.114: J21.1 65.98,65 68.3,62.68 77.37,62.68 79.02,61.03 79.02,51.49 81.15,49.35 81.15,45.97 81.65,45.47 81.65,44.58 81.22,44.16 81.22,43.52 80.8,43.1 80.8,40.94 80.38,40.53 79.92,40.53 v2(79.6,40.2)
P5_0: length 123.5
  TOP w0.114: v1(64.21,37.53) 67.48,37.53 67.51,37.57 76.07,37.57 78.31,39.8 78.74,39.8 79.23,40.3 U1.N7
  L03_SIG w0.114: J4.1 64.21,63.73 v1(64.21,37.53) 65.38,37.53 67.85,35.06 67.85,24.27 v1(68.43,23.69)
  L06_SIG w0.114: v1(9,23.09) 10.14,24.23 15.82,24.23 16.76,25.17 31.62,25.17 32.59,24.2 61.49,24.2 62.61,25.32 66.8,25.32 v1(68.43,23.69)
  BOTTOM w0.114: R159.2 v1(9,23.09)
P5_1: length 114.4
  TOP w0.114: U1.L8 v2(80.25,39.55)
  L03_SIG w0.114: v1(9,27.01) 8.94,27.07 v1(8.94,36.45) ; v1(60.43,43.88) 60.68,44.14 60.68,45.64 62.43,47.39 62.43,52.24 60.68,53.99 60.68,62.55 60.68,62.68 60.68,64.72 J4.2
  L06_SIG w0.114: v2(80.25,39.55) 79.92,39.88 71.42,39.88 67.92,43.38 60.93,43.38 v1(60.43,43.88) 60.3,44.01 56.03,44.01 51.69,39.67 49.83,39.67 47.83,41.67 47.16,41.67 46.29,42.55 41.64,42.55 39.95,40.86 38.96,40.86 37.97,41.85 36.55,41.85 36.14,41.45 36.14,39.64 35.81,39.31 32.79,39.31 31.33,37.85 10.33,37.85 v1(8.94,36.45)
  BOTTOM w0.114: v1(9,27.01) R156.2
P5_2: length 49.3
  TOP w0.114: U1.M8 v2(79.6,39.55)
  L03_SIG w0.114: v1(60.55,41.34) 59.92,41.98 59.92,48.63 v1(61.87,50.59) 61.87,52.11 60.17,53.81 60.17,60.85 57.86,63.16 J4.3
  L06_SIG w0.114: v1(60.55,41.34) 61.09,40.81 70.04,40.81 71.29,39.55 v2(79.6,39.55)
  BOTTOM w0.114: R204.2 R93.1 61.96,50.68 v1(61.87,50.59)
P5_3: length 57.7
  TOP w0.114: v1(61.57,37.38) 61.95,37 67.28,37 67.59,37.3 76.29,37.3 78.51,39.52 78.92,39.52 U1.N8
  L03_SIG w0.114: J4.4 56.51,66.18 61.14,66.18 61.75,65.58 61.75,64.58 61.09,63.92 61.09,54.4 v1(62.59,52.9) 62.97,52.52 62.97,47.08 61.42,45.53 61.42,42.99 61.57,42.84 v1(61.57,37.38)
  BOTTOM w0.114: v1(62.59,52.9) 62.59,53.28 62.33,53.54 R88.1
P5_4: length 55.1
  TOP w0.114: U1.L9 v2(80.25,38.9)
  L03_SIG w0.114: v1(57,37.15) 54.68,39.47 54.68,45.87 51.94,48.61 51.94,64.16 J4.5
  L06_SIG w0.114: v1(57,37.15) 57.24,36.91 65.58,36.91 66.89,38.22 74.35,38.22 75.35,39.23 79.92,39.23 v2(80.25,38.9)
P5_5: length 61.8
  TOP w0.114: U1.M9 v2(79.6,38.9)
  L03_SIG w0.114: v1(49.63,36.26) 49.63,45.66 50.88,46.91 50.88,52.6 50.24,53.23 J4.6
  L06_SIG w0.114: v2(79.6,38.9) 76.6,38.9 75.64,37.94 67.06,37.94 65.76,36.64 55.27,36.64 53.95,35.32 52.6,35.32 51.66,36.26 v1(49.63,36.26)
P5_6: length 58.6
  TOP w0.114: U1.N9 78.53,39.19 76.35,37.01 67.67,37.01 67.42,36.75 61.21,36.75 v1(60.17,37.79)
  L03_SIG w0.114: v1(60.17,37.79) 60.17,40.33 59.62,40.88 59.62,41.28 57.63,43.27 57.63,45.28 55.85,47.06 55.85,51.23 56.74,52.12 56.74,62.02 54.08,64.69 54.08,65.52 53.42,66.18 48.89,66.18 J4.7
P5_7: length 41.7
  TOP w0.114: U1.N10 78.3,38.54 76.35,36.59 70.64,36.59 v1(70.51,36.47) ; v1(66.01,63.31) 67.46,63.31 68.02,63.87 J21.3
  L03_SIG w0.114: v1(70.51,36.47) 70.51,46.8 67.16,50.16 67.16,62.17 v1(66.01,63.31)
P5LP0_1: length 35.6
  TOP w0.114: J6.4 5.83,36.8 7.11,36.8 7.4,37.08 28.59,37.08 v1(29.13,36.54) ; U2.49 34.91,31.89 v1(34.24,31.22)
  L06_SIG w0.114: v1(34.24,31.22) 33.83,31.22 32.66,32.38 32.66,32.7 31.56,33.8 31.37,33.8 29.72,35.46 29.72,35.96 v1(29.13,36.54)
P5LP0_2: length 48.7
  TOP w0.114: U2.50 35.56,31.49 33.73,29.66 33.73,21.34 33.93,21.13 33.93,19.02 33.66,18.75 26.45,18.75 21.26,13.56 14.5,13.56 12.8,11.86 7.75,11.86 v1(7.06,12.55)
  BOTTOM w0.114: v1(7.06,12.55) 7.06,11.6 J7.1
P5LP0_3: length 46.7
  TOP w0.114: J7.3 5.1,11.58 12.97,11.58 14.66,13.28 21.42,13.28 26.63,18.49 33.86,18.49 34.29,18.92 34.29,21.39 33.99,21.69 33.99,29.56 35.52,31.09 U2.51
P5LP0_5: length 54.3
  TOP w0.114: U2.54 38.24,28.97 37.34,28.07 37.34,25.58 38.46,24.45 44.75,24.45 45.42,25.11 45.42,26.17 45.56,26.31 45.99,26.31 v1(46.23,26.08) ; U2.30 39.04,39.62 37.67,41 v1(37.03,41)
  L03_SIG w0.114: v1(46.23,26.08) 46.51,26.36 47.25,26.36 47.73,26.84 48.29,26.84 49.23,27.78 49.23,29.2 52.53,32.5 52.53,35.48 TP25.1
  L06_SIG w0.114: v1(37.03,41) 39.57,38.46 43.12,38.46 43.59,38.93 48.56,38.93 50.09,37.41 52.59,37.41 52.93,37.06 TP25.1
  BOTTOM w0.114: TP25.1 52.63,36.19 51.84,36.19 51.78,36.13 U25.10
P5LP0_6: length 54.1
  TOP w0.114: U2.37 34.48,36.69 v1(33.48,37.69) ; U2.55 38.64,28.96 37.62,27.94 37.62,25.7 38.6,24.71 44.63,24.71 45.16,25.25 45.16,26.26 45.47,26.57 45.91,26.57 v1(46.23,26.89)
  L03_SIG w0.114: v1(52.32,36.9) 52.29,36.9 52.17,36.78 52.17,32.66 48.87,29.35 48.87,27.89 48.15,27.17 47.6,27.17 47.05,26.62 46.5,26.62 v1(46.23,26.89)
  L06_SIG w0.114: v1(33.48,37.69) 34.02,37.15 34.02,37.14 34.26,36.9 36.3,36.9 37.29,37.9 43.06,37.9 43.76,38.6 48.26,38.6 49.96,36.9 v1(52.32,36.9)
  BOTTOM w0.203: SH1.2 51.83,36.56 52.17,36.9 v1(52.32,36.9)
P5LP0_7: length 50.4
  TOP w0.114: v1(7.21,21.86) 7.21,16.12 5.51,14.42 J7.5 ; U2.56 39.04,28.64 39.62,28.06 v1(39.62,25.76)
  L06_SIG w0.114: v1(7.21,21.86) 6.65,22.43 6.65,23.4 8.05,24.81 15.65,24.81 16.59,25.75 28.42,25.75 29.64,26.97 32.56,26.97 33.77,25.76 v1(39.62,25.76)
P5LP1_2: length 82.8
  TOP w0.114: v1(15.6,29.74) 15.4,29.54 SW3.1 SW3.2 ; v1(52.43,41.67) 52.43,41.37 51.08,40.02 49.45,40.02 49.05,39.62 49.05,37.79 47.15,35.89 U2.13
  L06_SIG w0.114: v1(15.6,29.74) 9.64,29.74 7.24,32.14 7.24,36.83 9.32,38.91 30.36,38.91 32.13,40.68 32.13,43.76 33.66,45.28 48.23,45.28 49.66,43.86 50.67,43.86 52.43,42.11 v1(52.43,41.67)
P5LP1_3: length 81.9
  TOP w0.114: R56.1 25.1,27.1 25.1,28.62 v1(24.48,29.24) ; v1(51.18,41.04) 50.9,41.32 50.29,41.32 48.79,39.82 48.79,37.99 47.09,36.29 U2.14
  L06_SIG w0.114: v1(24.48,29.24) 22.97,30.75 10.24,30.75 8.38,32.61 8.38,36.69 9.8,38.1 31.22,38.1 33.88,40.76 33.88,41.75 36.54,44.4 47.72,44.4 51.08,41.04 v1(51.18,41.04)
P5LP1_4: length 82.3
  TOP w0.114: U2.15 47.09,36.69 48.55,38.15 48.55,39.96 50.19,41.6 50.52,41.6 50.98,42.05 50.98,42.84 v1(50.52,43.3) ; R54.1 22.54,28.46 21.78,29.23 v1(21.03,29.23)
  L06_SIG w0.114: v1(50.52,43.3) 49.76,43.3 48.03,45.03 33.81,45.03 32.38,43.6 32.38,40.55 30.45,38.61 9.47,38.61 7.62,36.75 7.62,32.3 9.7,30.22 20.04,30.22 v1(21.03,29.23)
P5LP1_5: length 81.2
  TOP w0.114: R55.1 23.9,27.13 23.9,28.63 v1(23.33,29.2) ; v1(50.5,42.28) 48.29,40.07 48.29,38.28 47.09,37.09 U2.16
  L06_SIG w0.114: v1(50.5,42.28) 50.24,42.28 47.75,44.77 33.91,44.77 32.64,43.5 32.64,40.26 30.72,38.35 9.67,38.35 8,36.68 8,32.45 9.96,30.5 22.03,30.5 v1(23.33,29.2)
P5LP2_0: length 1.5
  TOP w0.114: U2.62 41.44,29.09 v1(41.63,28.9)
P5LP2_2: length 3.5
  TOP w0.114: v1(42.9,27.03) 42.52,27.41 42.52,29.41 42.24,29.69 U2.64
P5LP2_3: length 3.8
  TOP w0.114: v1(44.04,27.03) 42.77,28.3 42.77,29.53 42.64,29.67 U2.65
P5LP2_4: length 2.5
  TOP w0.114: v1(44.02,28.17) 43.04,29.15 U2.66
P5LP3_0: length 46
  TOP w0.114: U2.29 39.44,39.92 38.43,40.93 38.43,42.42 36.96,43.88 30.99,43.88 30.23,43.12 30.23,41.24 26.35,37.36 6.84,37.36 v1(6.76,37.28)
  L06_SIG w0.114: v1(6.76,37.28) 6.76,34.7 J6.8
P5LP3_4: length 45.1
  TOP w0.114: J6.11 3.53,28.93 10.27,28.93 12.17,30.83 22.89,30.83 v1(26.24,34.18) ; v1(35.64,39.85) 36.27,39.22 37.54,39.22 37.84,38.92 U2.33
  BOTTOM w0.114: v1(35.64,39.85) 36.6,38.89 36.6,37.08 35.49,35.97 27.19,35.97 26.44,35.22 26.44,34.38 v1(26.24,34.18)
P5LP3_5: length 40.9
  TOP w0.114: v1(24.49,30.88) 23.59,30.88 23.27,30.56 12.34,30.56 10.44,28.65 5.79,28.65 J6.12 ; v1(35.64,38.58) 35.93,38.29 U2.34
  BOTTOM w0.114: v1(24.49,30.88) 24.49,32.38 25.68,33.57 25.68,35.22 27.69,37.24 30.88,37.24 31.29,36.82 35.64,36.82 36.09,37.28 36.09,38.13 v1(35.64,38.58)
P5LP3_6: length 47.5
  TOP w0.114: v1(34.49,37.69) 35.1,37.09 U2.36
  L03_SIG w0.114: v1(34.44,27.6) 34.44,30.32 33.73,31.03 33.73,33.6 34.04,33.91 34.04,37.24 v1(34.49,37.69)
  L06_SIG w0.114: v1(34.44,27.6) 34.04,27.2 32.87,27.2 32.72,27.35 29.48,27.35 28.19,26.05 16.54,26.05 15.57,25.09 7.47,25.09 6.22,23.84 3.51,23.84 J6.15
P5LP15_0: length 58.2
  TOP w0.114: U2.27 40.24,40.39 v1(40.34,40.49) ; v1(21.03,11.99) SW4.2 SW4.1
  L03_SIG w0.114: v1(40.34,40.49) 40.34,37.91 40.84,37.41 40.84,27.17 40.56,26.89 40.56,18.41 41.35,17.63 41.35,11.42 v1(40.61,10.69)
  L06_SIG w0.114: v1(40.61,10.69) 22.33,10.69 v1(21.03,11.99)
P5LP15_4: length 47.5
  TOP w0.114: v1(41.76,27.03) 40.82,27.97 40.82,29.39 40.64,29.57 U2.60
  L03_SIG w0.114: v1(41.76,27.03) 41.76,22.12 v1(42.09,21.79)
  L06_SIG w0.114: v1(42.09,21.79) 41.83,22.04 24.31,22.04 22.76,20.49 8.2,20.49 7.21,19.5 J7.9
P5LP_SIO_VREF: length 17.7
  TOP w0.114: U2.48 34.69,32.29 v1(34.62,32.36)
  L03_SIG w0.114: v1(38.68,43.68) 38.68,39.86 34.42,35.6 34.42,33.71 34.19,33.48 34.19,32.79 v1(34.62,32.36)
  BOTTOM w0.114: R119.2 R123.1 38.57,43.79 v1(38.68,43.68)
P5LP_SSEL_P12_4: length 7.4
  BOTTOM w0.114: R83.2 63.73,54.93 63.17,54.37 59.03,54.37 58.95,54.45 U17.5
P5LP_SWDCLK: length 68.6
  TOP w0.114: U2.12 46.29,35.49 v1(47.8,33.98)
  L03_SIG w0.114: v1(47.85,18.74) 47.85,22.3 45.75,24.41 45.75,27.42 46.06,27.74 47.1,27.74 47.4,28.03 47.4,31.03 47.65,31.29 47.65,33.83 v1(47.8,33.98)
  L06_SIG w0.114: J7.8 3.3,15.92 23.9,15.92 26.26,18.28 47.4,18.28 v1(47.85,18.74)
P5LP_SWDIO: length 59.9
  TOP w0.114: U2.11 46.11,35.09 46.81,34.39 v1(46.81,33.77)
  L03_SIG w0.114: v1(46.81,33.77) 46.81,33.42 45.16,31.77 45.16,23.33 v1(45.77,22.73)
  L06_SIG w0.114: J7.10 3.91,21.15 22.61,21.15 24,22.55 45.59,22.55 v1(45.77,22.73)
P5LP_USB_DM: length 71.9
  TOP w0.203: R34.1 42.06,42.85 42.06,44.03 41.46,44.63 39.63,44.63 37.58,46.69 29.41,46.69 21.67,38.94 9.36,38.94 8.28,40.01 8.28,47.55 9.65,48.92 9.65,49.94 10.08,50.37 10.08,52.32 9.35,53.06 9.35,54.8 9.79,55.25 10.7,55.25 v1(10.96,55.51) ; J10.A7 7.59,51.97 7.61,51.99 8.52,51.99 8.74,51.78 8.74,51.58 v1(8.44,51.28)
  L06_SIG w0.203: v1(8.44,51.28) 8.73,51 8.73,50.8 8.52,50.6 7.93,50.6 7.67,50.86 7.67,52.03 7.22,52.48 5.54,52.48 J10.B7
  BOTTOM w0.229: v1(8.44,51.28) 8.76,51.6 8.76,52.17 9.49,52.9 TVS2.5 9.49,54.55 10.13,55.19 10.65,55.19 v1(10.96,55.51)
P5LP_USB_DP: length 71.8
  TOP w0.203: R35.1 42.47,42.83 42.47,44.2 41.63,45.03 39.8,45.03 37.74,47.09 29.24,47.09 21.5,39.34 9.53,39.34 8.69,40.18 8.69,47.38 10.06,48.75 10.06,49.77 10.49,50.2 10.49,52.49 9.75,53.23 9.75,54.64 9.96,54.84 10.76,54.84 v1(10.96,54.64) ; J10.A6 7.59,52.47 7.65,52.4 8.69,52.4 9.14,51.95 9.14,51.56 v1(9.42,51.28)
  L06_SIG w0.203: v1(9.42,51.28) 9.13,51 9.13,50.63 8.69,50.19 7.76,50.19 7.26,50.69 7.26,51.86 7.05,52.07 5.65,52.07 J10.B6
  BOTTOM w0.229: v1(10.96,54.64) 10.83,54.77 10.83,54.76 10.31,54.76 10.14,54.59 TVS2.4 10.14,52.94 9.19,51.99 9.19,51.5 v1(9.42,51.28)
P5LP_VCCA: length 6.2
  TOP w0.198: U2.42 35,34.69 33.82,33.5 C40.1
P5LP_VCCD: length 23.7
  TOP w0.198: v1(40.22,27.39) 40.22,28.2 39.44,28.98 U2.57 ; C30.2 40.87,40.84 40.87,39.92 40.64,39.69 U2.26
  TOP w0.381: C30.2 40.25,41.46 v1(39.42,41.46)
  L03_SIG w0.381: v1(40.22,27.39) 39.18,28.44 39.18,41.22 v1(39.42,41.46)
  BOTTOM w0.381: C132.1 40.59,27.03 v1(40.22,27.39)
P5LP_VDD: length 82.9
  TOP w0.198: v1(40.34,29.08) 40.24,29.18 U2.59 ; v1(44.02,29.18) 43.89,29.18 43.44,29.64 U2.67 ; v1(35.53,37.74) 35.78,37.49 U2.35 ; v1(36.78,30.45) 36.94,30.29 U2.52 ; v1(45.67,37.69) 45.47,37.49 U2.17 ; U2.24 41.44,39.26 v1(41.35,39.34) ; U2.44 35.17,33.89 v1(35.05,34.01)
  TOP w0.381: v1(35.53,37.74) 35.38,37.74 C34.1 34.42,38.69 C32.1 34.42,40.59 v1(34.73,40.9) ; R37.1 v1(47.47,40.84)
  L05_MIX w0.381: 2.26,8.25 J7.2 ; J7.2 3.35,9.34 ; J7.2 1.17,9.34 ; J7.2 2.26,10.43 ; J6.1 2.26,41.46 ; J6.1 2.26,39.27 ; J6.1 3.35,40.37 ; J6.1 1.17,40.37
  L06_SIG w0.381: 70.51,26.59 67.63,26.59 ; v1(40.34,29.08) 41.08,29.83 43.37,29.83 v1(44.02,29.18) 45.03,28.17 45.03,26.1 45.69,25.45 50.6,25.45 51.84,26.7
  L06_SIG w0.635: 67.63,26.59 67.53,26.7 51.84,26.7 ; 70.51,26.59 70.66,26.74 v1(75.33,26.74) 76.05,26.02 76.05,23.87 75.62,23.44 74.55,23.44 v1(74.17,23.82)
  BOTTOM w0.254: U23.1 44.27,42.39 44.24,42.36 44.24,42.23 43.76,41.75 v1(43.76,41.73) ; C56.2 55.96,58.01 U17.20
  BOTTOM w0.381: v1(41.35,39.34) 40.73,38.72 C106.1 40.45,38.71 C107.1 ; C116.1 36.44,34.05 C118.1 35.08,34.04 v1(35.05,34.01) ; v1(45.67,37.69) 45.16,37.19 C113.1 45.16,35.54 C115.1 ; C123.1 40.51,29.26 v1(40.34,29.08) ; v1(54.38,59.07) 55.06,58.39 v1(55.07,58.39) 55.45,58.01 C56.2 ; v1(43.76,41.73) v1(43.76,41)
  BOTTOM w0.635: v1(74.17,23.82) 74.42,24.07 R157.1 ; v1(75.33,26.74) 74.98,26.74 R155.1
  vias: v1(44.65,41.73) v1(44.65,41) v1(106.07,62.28) v1(106.67,61.68)
P5LP_XRES_L: length 63.5
  TOP w0.114: U2.10 45.54,34.69 v1(45.82,34.41) ; J7.6 3.46,15.62 6.17,15.62 6.96,16.41 6.96,20.03 v1(6.71,20.29)
  L03_SIG w0.114: v1(45.82,34.41) 45.82,34.13 44.86,33.16 44.86,22.62 v1(45.44,22.04)
  L06_SIG w0.114: v1(6.71,20.29) 7.24,20.82 22.71,20.82 24.18,22.29 45.19,22.29 v1(45.44,22.04)
P6_0: length 112.3
  TOP w0.114: U1.M10 v2(79.6,38.25)
  L03_SIG w0.114: J3.10 16.4,63.16 12.14,63.16 8.94,59.96 8.94,53.99 7.34,52.39 7.34,49.6 8.23,48.71 8.23,44.52 8.86,43.88 8.86,39.08 10.14,37.81 v1(10.14,35.27)
  L06_SIG w0.114: v2(79.6,38.25) 76.38,38.25 75.82,37.69 67.23,37.69 65.94,36.39 55.52,36.39 54.18,35.04 53.76,35.04 53.64,35.04 52.48,35.04 51.79,35.74 49.32,35.74 49.02,36.03 32.33,36.03 30.8,37.57 12.44,37.57 v1(10.14,35.27)
  BOTTOM w0.114: R141.2 v1(10.14,35.27)
P6_1: length 121.3
  TOP w0.114: U1.L10 v2(80.25,38.25)
  L03_SIG w0.114: J3.9 18.62,62.84 12.2,62.84 9.25,59.89 9.25,53.92 7.64,52.31 7.64,49.66 8.63,48.67 8.63,44.83 9.25,44.21 9.25,39.41 11.05,37.61 v1(11.05,31.93)
  L06_SIG w0.114: v1(11.05,31.93) 16.43,37.31 30.66,37.31 32.19,35.78 48.87,35.78 49.17,35.48 51.54,35.48 52.25,34.76 54.41,34.76 55.78,36.14 66.14,36.14 67.44,37.43 76.02,37.43 76.52,37.93 79.79,37.93 80.12,38.25 v2(80.25,38.25)
  BOTTOM w0.114: v1(11.05,31.93) 10.52,31.4 10.52,30.55 10.18,30.21 R150.2
P6_2: length 33.5
  TOP w0.114: J2.15 69.58,15.18 v1(76.56,15.18) ; U1.L11 v2(80.25,37.6)
  L03_SIG w0.114: v1(76.56,15.18) 76.56,17.29 77.24,17.98 77.24,33.57 79.92,36.25 79.92,37.28 v2(80.25,37.6)
P6_3: length 86.7
  TOP w0.114: J2.17 71.82,18 76.17,18 v1(76.3,18.13) ; U1.M11 v2(79.6,37.6)
  L03_SIG w0.114: v2(79.6,37.6) 76.73,34.74 76.73,18.56 v1(76.3,18.13)
  L06_SIG w0.114: v2(79.6,37.6) 79.79,37.6 80.11,37.93 81.21,37.93 81.76,38.47 82.41,38.47 82.6,38.67 85.42,38.67 85.7,38.39 85.7,38.12 85.89,37.93 87.34,37.93 87.99,37.28 88.62,37.28 88.89,37.55 92.92,37.55 93.57,38.19 123.29,38.19 125.05,36.44 133.29,36.44 v1(134.83,34.9)
  BOTTOM w0.114: R145.2 v1(134.83,34.9)
P6_4: length 58
  TOP w0.114: v1(76.33,7.31) 76.06,7.04 56.34,7.04 55.91,6.6 J12.6 ; v2(77.6,37.36) 78.13,37.89 U1.N11
  L03_SIG w0.114: v1(76.33,7.31) 75.79,7.84 75.79,18.32 76.43,18.95 76.43,36.19 v2(77.6,37.36)
  BOTTOM w0.114: J11.6 76.3,7.28 v1(76.33,7.31)
P6_5: length 56.7
  TOP w0.114: U1.M12 v2(79.6,36.95) ; J12.8 57.18,6.22 57.72,6.76 76.89,6.76 v1(77.34,7.21)
  L03_SIG w0.114: v2(79.6,36.95) 76.99,34.34 76.99,18.15 76.07,17.24 76.07,8.48 v1(77.34,7.21)
  BOTTOM w0.114: v1(77.34,7.21) 77.57,6.98 J11.8
P6_6: length 46.8
  TOP w0.114: v1(74.52,10.23) 74.73,10.23 77.34,12.84 77.34,20.95 79.25,22.85 79.25,31.51 78.16,32.61 78.16,34.87 77.85,35.17 72.9,35.17 72.54,34.82 72.03,34.82 71.86,34.99 71.86,35.81 72.01,35.96 77.96,35.96 U1.N12
  BOTTOM w0.114: v1(74.52,10.23) 74.07,10.69 72.05,10.69 R192.1
P6_7: length 33.3
  TOP w0.114: U1.M13 79.88,36.11 78.69,34.92 78.69,33.55 79.71,32.53 79.71,22.67 77.67,20.64 77.67,11.57 77.09,10.99 76.68,10.99 76.43,10.74 76.43,9.47 v1(76.94,8.96)
  BOTTOM w0.114: R191.1 78.48,10.46 77.57,10.46 77.47,10.36 77.47,9.12 77.31,8.96 v1(76.94,8.96)
P6_VDD: length 90.2
  TOP w0.381: TP21.1 54.01,38.58 54.89,39.46 54.89,46.45 v1(56.47,48.02) ; J26.2 112.75,53.35 v1(110.43,51.03) R12.1 110.43,49.82 109.45,48.84 ; R40.2 v1(30.56,36.68) ; R43.2 v1(30.56,35.41)
  L03_SIG w0.381: v1(58.12,58.39) 58.12,49.67 v1(56.47,48.02)
  L03_SIG w0.508: v1(91.03,46.55) 91.92,47.44 v1(91.92,51.12)
  L03_SIG w0.635: J1.7 29.84,16.74 28.35,18.23 27.15,18.23 26.58,18.81 26.58,33.15 27.66,34.23 29.38,34.23 v1(30.56,35.41) v1(30.56,36.68)
  L05_MIX w0.381: 111.67,54.81 J26.2 ; J26.2 113.83,54.81 ; J26.2 112.75,53.72 ; J26.2 112.75,55.89 ; J14.6 21.12,3.02 ; J14.6 18.94,3.02 ; J14.6 20.03,1.93 ; J14.6 20.03,4.11 ; 28.83,16.74 J1.7 ; J1.7 29.92,17.83 ; J1.7 29.92,15.65 ; J1.7 31.01,16.74 ; 52.76,37.49 TP21.1 ; TP21.1 52.76,39.67 ; TP21.1 51.66,38.58 ; TP21.1 53.85,38.58
  BOTTOM w0.203: U25.2 51.78,34.27 U25.3 51.78,31.96 R148.2
  BOTTOM w0.254: C55.1 56.46,57.25 U17.1
  BOTTOM w0.381: C55.1 57.73,58.01 v1(58.12,58.39) ; v1(91.92,51.12) 91.37,51.12 91.22,50.98 91.22,50.98 90.84,50.59 90.83,50.58 90.64,50.39 90.63,50.39 90.62,50.37 90.62,50.37 C82.2 90.39,48.95 89.98,48.55 U22.5 ; R104.1 v1(56.47,48.02)
  vias: v1(46.71,2.08) v1(47.93,2.11) v1(52.15,29.58) v1(52.3,30.68) v1(108.32,48.06) v1(109.18,48.06) v1(116.26,55.42) v1(116.28,54.15) v1(117.07,54.81) v1(119.99,39.95) v1(121.01,39.95) v1(122.15,39.95)
P7_0: length 50.4
  TOP w0.114: v1(76.94,9.72) 77.95,10.74 77.95,20.49 80.14,22.67 80.14,32.53 79.45,33.22 79.45,34.03 80.53,35.11 U1.L13
  L06_SIG w0.114: v1(59.08,10.77) 60.51,9.34 69.08,9.34 69.62,9.88 73.28,9.88 73.82,9.34 76.56,9.34 v1(76.94,9.72)
  BOTTOM w0.114: R181.1 v1(59.08,10.77) R189.1
P7_1: length 17.7
  TOP w0.114: U1.L12 v2(80.25,36.95) ; v1(67.41,39.44) 67.68,39.17 C33.2
  L03_SIG w0.114: v1(67.41,39.44) 68.81,38.04 v1(68.81,36.52)
  L06_SIG w0.114: v2(80.25,36.95) 79.89,36.59 76.81,36.59 76.25,37.15 69.44,37.15 v1(68.81,36.52)
P7_2: length 21
  TOP w0.114: U1.K13 81.18,35.3 79.91,34.03 v1(79.91,33.47) ; C31.1 72.17,41.33 v1(72.87,42.03)
  L03_SIG w0.114: v1(73,34.05) 73.08,34.12 73.08,40.48 72.87,40.68 v1(72.87,42.03)
  L06_SIG w0.114: v1(73,34.05) 79.33,34.05 v1(79.91,33.47)
P7_3: length 19.1
  TOP w0.114: U1.N13 79.09,36.59 78.13,35.63 72.62,35.63 v1(72.36,35.37) ; C29.1 72.26,43.5 v1(72.59,43.17)
  L03_SIG w0.114: v1(72.36,35.37) 72.75,35.76 72.75,40.23 72.36,40.61 72.36,42.94 v1(72.59,43.17)
  BOTTOM w0.254: v1(72.36,35.37) 71.6,34.61 R146.2
P7_4: length 40.6
  TOP w0.114: U1.K11 v2(80.9,37.6)
  L03_SIG w0.114: v2(80.9,37.6) 80.57,37.28 80.57,35.58 77.5,32.5 77.5,15.13 76.86,14.5 v1(76.86,13.33)
  BOTTOM w0.114: v1(76.86,13.33) 75.92,12.39 74.52,12.39 73.51,11.37 67.28,11.37 66.75,11.9 R178.1 R186.1
P7_5: length 44.8
  TOP w0.114: v1(79.53,11.22) 80.34,12.03 80.34,22.09 80.77,22.52 80.77,31.64 81.64,32.5 81.64,36.39 U1.J13
  L06_SIG w0.114: v1(79.53,11.22) 77.85,11.22 77.06,12.01 76.48,12.01 75.45,10.97 64.52,10.97 v1(64.26,10.72)
  BOTTOM w0.114: R179.1 v1(64.26,10.72) R187.1
P7_6: length 47
  TOP w0.114: U1.J12 v2(81.55,36.95)
  L03_SIG w0.114: v2(81.55,36.95) 80.98,36.38 80.98,35.58 77.75,32.35 77.75,13.35 76.81,12.41 v1(76.81,11.5)
  L06_SIG w0.114: v1(61.06,10.86) 61.71,10.22 64.86,10.22 65.35,10.71 76.12,10.71 v1(76.81,11.5)
  BOTTOM w0.114: R188.1 61.27,10.66 v1(61.06,10.86) 61.27,11.07 R180.1
P7_7: length 6.2
  TOP w0.114: U1.J11 v2(81.55,37.6)
  BOTTOM w0.114: v2(81.55,37.6) 81.22,37.28 79.34,37.28 R142.1 78.13,36.07 C27.2
P8_0: length 24.6
  TOP w0.114: v2(82.22,34.97) 82.22,36.32 U1.H13
  TOP w0.203: R63.2 88.62,15.56 v1(88.24,15.94)
  L06_SIG w0.203: v1(88.24,15.94) 84.99,19.19 84.99,30.19 82.12,33.06 82.12,34.87 v2(82.22,34.97)
